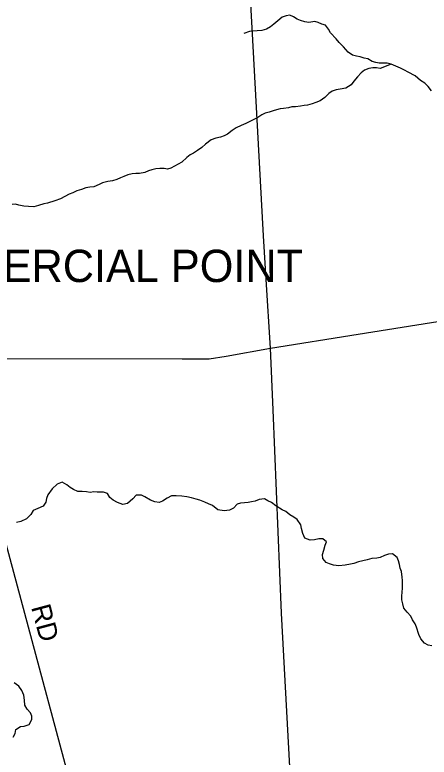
# Model space of a CAD drawing. Extents: x 1643459 to 2064572, y 425441 to 780708.
# Drawn here: x 1816774 to 1823182, y 638720 to 650201 of the extents above; entities that cross this region are included whole.
import ezdxf

# ---------------------------------------------------------------- set-up
doc = ezdxf.new("R2010")
doc.units = 0
for name, color, linetype in [('GM_P_County_Alignment', 7, 'Continuous'), ('GM_X_Major_River', 7, 'Continuous'), ('GM_X_Major_River_Text', 7, 'Continuous'), ('GM_X_US_Route', 7, 'Continuous'), ('RD_X_Text', 7, 'Continuous')]:
    doc.layers.add(name, color=color, linetype=linetype)

msp = doc.modelspace()

# ---------------------------------------------------------------- linework, layer by layer
at = {"layer": 'GM_X_Major_River_Text'}
msp.add_lwpolyline([(1815864, 644884), (1817755, 637853), (1818229, 635847), (1818377, 635282)], dxfattribs=at)
at = {"layer": 'GM_X_US_Route'}
for points in [[(1822592, 649440), (1822530, 649451), (1822460, 649453), (1822410, 649456), (1822358, 649464), (1822300, 649479), (1822233, 649521), (1822175, 649532), (1822115, 649552), (1822057, 649563), (1821995, 649579), (1821930, 649626), (1821858, 649704), (1821791, 649775), (1821741, 649831), (1821654, 649922), (1821623, 649978), (1821577, 650040), (1821521, 650059), (1821467, 650085), (1821414, 650098), (1821323, 650081), (1821257, 650091), (1821192, 650112), (1821138, 650134), (1821086, 650169), (1821026, 650197), (1820972, 650188), (1820910, 650164), (1820843, 650109), (1820781, 650056), (1820726, 650016), (1820664, 649979), (1820592, 649958), (1820524, 649955), (1820456, 649947), (1820403, 649942), (1820317, 649911)], [(1822592, 649440), (1822422, 649370), (1822368, 649380), (1822308, 649383), (1822247, 649370), (1822183, 649344), (1822131, 649303), (1822072, 649244), (1822017, 649174), (1821973, 649119), (1821892, 649066), (1821806, 649051), (1821742, 649041), (1821684, 649020), (1821629, 648982), (1821569, 648923), (1821498, 648872), (1821428, 648847), (1821370, 648827), (1821300, 648806), (1821249, 648798), (1821191, 648787), (1821117, 648780), (1821057, 648776), (1821005, 648765), (1820931, 648754), (1820875, 648746), (1820819, 648731), (1820768, 648717), (1820708, 648698), (1820648, 648679), (1820596, 648653), (1820531, 648614), (1820471, 648582), (1820409, 648553), (1820348, 648522), (1820274, 648489), (1820196, 648451), (1820137, 648412), (1820063, 648353), (1820012, 648331), (1819954, 648310), (1819882, 648293), (1819808, 648268), (1819721, 648203), (1819664, 648151), (1819600, 648102), (1819538, 648063), (1819487, 648035), (1819435, 647996), (1819356, 647921), (1819302, 647889), (1819244, 647862), (1819189, 647827), (1819137, 647815), (1819085, 647826), (1819015, 647826), (1818955, 647819), (1818893, 647803), (1818839, 647786), (1818784, 647763), (1818702, 647747), (1818644, 647746), (1818588, 647743), (1818522, 647725), (1818462, 647700), (1818407, 647678), (1818351, 647653), (1818283, 647636), (1818211, 647622), (1818132, 647605), (1818076, 647576), (1817996, 647539), (1817936, 647535), (1817873, 647524), (1817805, 647501), (1817733, 647477), (1817669, 647450), (1817614, 647425), (1817478, 647356), (1817391, 647325), (1817279, 647288), (1817221, 647277), (1817138, 647250), (1817066, 647230), (1816984, 647237), (1816912, 647242), (1816836, 647258), (1816786, 647271), (1816732, 647265)], [(1823217, 649027), (1823165, 649091), (1823116, 649142), (1823048, 649184), (1822965, 649257), (1822855, 649316), (1822798, 649344), (1822738, 649375), (1822664, 649409), (1822592, 649440)], [(1819128, 642724), (1819060, 642680), (1819005, 642659), (1818939, 642670), (1818870, 642694), (1818786, 642747), (1818734, 642773), (1818650, 642774), (1818600, 642713), (1818519, 642642), (1818443, 642628), (1818361, 642659), (1818295, 642694), (1818242, 642738), (1818206, 642800), (1818144, 642817), (1818046, 642820), (1817994, 642822), (1817938, 642811), (1817884, 642825), (1817818, 642828), (1817750, 642829), (1817680, 642859), (1817629, 642890), (1817577, 642934), (1817507, 642972), (1817431, 642941), (1817352, 642870), (1817285, 642779), (1817263, 642719), (1817252, 642666), (1817210, 642600), (1817131, 642563), (1817057, 642534), (1817020, 642474), (1816956, 642407), (1816867, 642364), (1816799, 642349)], [(1823224, 640444), (1823168, 640450), (1823110, 640485), (1823051, 640549), (1823023, 640619), (1822986, 640730), (1822965, 640782), (1822923, 640846), (1822896, 640900), (1822842, 640960), (1822789, 641025), (1822773, 641091), (1822760, 641153), (1822758, 641207), (1822763, 641278), (1822770, 641328), (1822768, 641402), (1822767, 641454), (1822765, 641506), (1822752, 641590), (1822735, 641644), (1822721, 641698), (1822706, 641754), (1822686, 641810), (1822614, 641862), (1822552, 641859), (1822490, 641840), (1822422, 641810), (1822370, 641797), (1822294, 641792), (1822225, 641770), (1822087, 641742), (1822015, 641716), (1821963, 641703), (1821884, 641690), (1821784, 641679), (1821702, 641689), (1821638, 641708), (1821587, 641732), (1821537, 641793), (1821532, 641855), (1821554, 641922), (1821571, 641998), (1821592, 642052), (1821536, 642096), (1821476, 642095), (1821410, 642083), (1821342, 642078), (1821258, 642109), (1821228, 642179), (1821205, 642257), (1821198, 642313), (1821140, 642397), (1821089, 642430), (1821025, 642470), (1820965, 642521), (1820908, 642547), (1820812, 642608), (1820741, 642658), (1820689, 642685), (1820635, 642717), (1820555, 642704), (1820491, 642681), (1820436, 642667), (1820384, 642658), (1820324, 642654), (1820264, 642647), (1820212, 642635), (1820155, 642570), (1820093, 642539), (1820013, 642530), (1819913, 642545), (1819832, 642613), (1819768, 642640), (1819712, 642664), (1819634, 642697), (1819578, 642709), (1819504, 642728), (1819434, 642745), (1819359, 642757), (1819267, 642762), (1819198, 642759), (1819128, 642724)], [(1816750, 639031), (1816777, 639085), (1816792, 639145), (1816864, 639192), (1816920, 639201), (1816996, 639223), (1817037, 639300), (1817036, 639354), (1817016, 639406), (1816965, 639464), (1816931, 639522), (1816922, 639600), (1816915, 639678), (1816883, 639752), (1816838, 639819), (1816764, 639871)]]:
    msp.add_lwpolyline(points, dxfattribs=at)
at = {"layer": 'RD_X_Text'}
for points in [[(1820662, 646105), (1820619, 646782), (1820453, 649809), (1820299, 652625), (1820262, 653273), (1820228, 653530), (1820198, 653775), (1819998, 655006), (1819838, 656017), (1819727, 656739), (1819684, 657028), (1819647, 657274), (1819565, 657827)], [(1820767, 644094), (1820727, 645047), (1820662, 646105)], [(1822086, 645262), (1823444, 645477)], [(1820727, 645047), (1820727, 645047), (1822086, 645262)], [(1819363, 644883), (1819778, 644882), (1820042, 644921), (1820727, 645047)], [(1813440, 644846), (1813785, 644856), (1814485, 644867), (1815864, 644884), (1819363, 644883)], [(1822283, 627226), (1822268, 627277), (1822178, 627481), (1822130, 627792), (1822000, 628118), (1821801, 629044), (1821579, 629722), (1821296, 634117), (1821212, 635208), (1821171, 635952), (1821122, 636856), (1820897, 640949), (1820767, 644094)]]:
    msp.add_lwpolyline(points, dxfattribs=at)

# ---------------------------------------------------------------- texts
at = {"layer": 'GM_P_County_Alignment'}
msp.add_text('COMMERCIAL POINT', height=500, rotation=0, dxfattribs=at).set_placement((1814470, 646068))
at = {"layer": 'GM_X_Major_River'}
msp.add_text('RD', height=300, rotation=284.9964, dxfattribs=at).set_placement((1817024, 641040))

doc.saveas('drawing.dxf')
